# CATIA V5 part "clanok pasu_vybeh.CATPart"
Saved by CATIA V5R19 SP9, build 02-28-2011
Part number: Part1
Material "Black": density 7860 kg/m3, Young's modulus 2e+11 Pa, Poisson ratio 0.266
Bounding box of the stored display mesh (mm): x -56 to 56, y 0 to 19.5, z -16.792 to 199.992
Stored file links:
  D:\CATIA FÓRUM\DISKUSE\clanok pasu_vybeh.CATPart
  C:\Program Files\Dassault Systemes\B19\win_b64\startup\materials\Catalog.CATMaterial
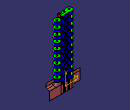
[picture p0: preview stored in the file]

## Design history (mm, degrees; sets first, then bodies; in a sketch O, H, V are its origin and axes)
AxisSystem1 "Main Pulling Direction.1": origin (0, 0, 0), X (1, 0, 0), Y (0, 0, -1), Z (0, 1, 0)
StDynAnalysisRootNodeFeature1 "CATStDynAnalysisRootNodeName"
Set1 "Core.1"
  DatumSurface1 to DatumSurface74
  DatumSurface75 "TrfSurface.322"
Set2 "Cavity.1"
  DatumSurface76
  DatumSurface77
  Boundary1: Boundary DatumSurface77
Set3
  Split1: ToCut Boundary1, Cutting (vertex [face of DatumSurface77 | face of DatumSurface77]; vertex [face of DatumSurface77 | face of DatumSurface77])
  Extrude1: Lim1 27, Lim2 0, Direction xy-plane, Element1 Split1
  Extrapol1: ToExtrapol edge of Extrude1, Support Extrude1, Length 38
  Split2: ToCut {split ToCut Boundary1, Cutting (vertex [face of DatumSurface77 | face of DatumSurface77]; vertex [face of DatumSurface77 | face of DatumSurface77])}, Cutting vertex [face of DatumSurface77 | face of DatumSurface77]
  Split3: ToCut Split2, Cutting (vertex [face of DatumSurface77 | face of DatumSurface77]; vertex [face of DatumSurface77 | face of DatumSurface77])
  Extrude2: Lim1 27, Lim2 0, Direction yz-plane, Element1 Split3
  Extrapol2: ToExtrapol edge of Extrude2, Support Extrude2, Length 27
  Curve1: Elements the part
  Fill1: Boundary ({fillboundary BoundaryWire edge of Extrude1}; Curve1; {fillboundary BoundaryWire edge of Extrapol2, Support Extrapol2}; edge of DatumSurface77)
  Split4: ToCut {split ToCut {split ToCut Boundary1, Cutting (vertex [face of DatumSurface77 | face of DatumSurface77]; vertex [face of DatumSurface77 | face of DatumSurface77])}, Cutting vertex [face of DatumSurface77 | face of DatumSurface77]}, Cutting vertex [face of DatumSurface77 | face of DatumSurface77]
  Split5: ToCut Split4, Cutting vertex [face of DatumSurface77 | face of DatumSurface77]
  Extrude3: Lim1 27, Lim2 0, Direction yz-plane, Element1 Split5
  Boundary2: Boundary edge of Extrude3, BoundaryFrom vertex [face of Extrude3], BoundaryTo {point type OnCurve, Support edge of Extrude3, Length 7.34}
  Boundary3: Boundary edge of Extrapol1, BoundaryFrom vertex [face of Extrapol1], BoundaryTo {point type OnCurve, Support edge of Extrapol1, Length 20.221}
  Blend1: StartLimit {blendlimit Support Extrude3, Curve Boundary2}, EndLimit {blendlimit Support Extrapol1, Curve Boundary3}
  StIsoparamCurveFeature1 "CATStIsoparamCurveFeatureName": Direction {line type PtDir, RefPoint {point type OnSurface, Support Extrapol1, Length 18.8172, Direction (0.825, 0, 0.5652)}, Direction (0, 0, 1000), LENGTH 0, LENGTH 10}, Support Extrapol1, Position {point type OnSurface, Support Extrapol1, Length 18.8172, Direction (0.825, 0, 0.5652)}, BRep face of Extrapol1
  Point1: type OnCurve, Support {split ToCut {split ToCut {split ToCut Boundary1, Cutting (vertex [face of DatumSurface77 | face of DatumSurface77]; vertex [face of DatumSurface77 | face of DatumSurface77])}, Cutting vertex [face of DatumSurface77 | face of DatumSurface77]}, Cutting vertex [face of DatumSurface77 | face of DatumSurface77]}, Length 5.442
  Boundary4: Boundary edge of Extrude3, BoundaryFrom vertex of Split4, BoundaryTo edge of Blend1
  Boundary5: Boundary edge of Extrapol1, BoundaryFrom edge of Blend1, BoundaryTo vertex of Split1
  StIsoparamCurveFeature2 "CATStIsoparamCurveFeatureName": Direction {line type PtDir, RefPoint {point type OnSurface, Support Blend1, Length 6.3176, Direction (-0.9945, -0.0872, 0.0576)}, Direction (1000.5583, 0, -0.2454), LENGTH 0, LENGTH 10}, Position {point type OnSurface, Support Blend1, Length 6.3176, Direction (-0.9945, -0.0872, 0.0576)}, BRep face of Blend1, Support Blend1
  Curve2: Elements the part
  Fill2: Boundary ({fillboundary BoundaryWire Boundary4, Support Extrude3}; {split ToCut {split ToCut {split ToCut Boundary1, Cutting (vertex [face of DatumSurface77 | face of DatumSurface77]; vertex [face of DatumSurface77 | face of DatumSurface77])}, Cutting vertex [face of DatumSurface77 | face of DatumSurface77]}, Cutting vertex [face of DatumSurface77 | face of DatumSurface77]}; Curve2; edge of Blend1)
  Split6: ToCut Blend1, Cutting StIsoparamCurveFeature2
  Split7: ToCut {split ToCut {split ToCut {split ToCut Boundary1, Cutting (vertex [face of DatumSurface77 | face of DatumSurface77]; vertex [face of DatumSurface77 | face of DatumSurface77])}, Cutting vertex [face of DatumSurface77 | face of DatumSurface77]}, Cutting vertex [face of DatumSurface77 | face of DatumSurface77]}, Cutting vertex [face of DatumSurface77 | face of DatumSurface77]
  Split8: ToCut Split7, Cutting edge of Fill2
  Curve3: Elements the part
  Fill3: Boundary ({fillboundary BoundaryWire edge of Blend1, Support Split6}; Curve3; Split8; {fillboundary BoundaryWire edge of Fill2, Support Fill2})
  Boundary6: Boundary edge of Extrapol1, BoundaryFrom edge of Fill3, BoundaryTo vertex of Split1
  Join1: Elements (Extrude3; Fill2; {split ToCut Blend1, Cutting StIsoparamCurveFeature2}; Split6; Fill3; Extrapol1; Fill1; Extrapol2)
  Blend2: StartLimit {blendlimit Curve edge of Fill3}, EndLimit {blendlimit Curve edge of Extrapol1}
  Join2: Elements (Join1; Blend2)
Set4 "Other.1"
  DatumSurface78 to DatumSurface116
Set5 "NoDraft_1deg.1"
  DatumSurface117 to DatumSurface149
Body1 (main body), material "Black"
  Sketch1 on xy-plane, origin (0, 0, 0), H (1, 0, 0), V (0, 1, 0)
    line L1 (0, 0) -> (20, 0)
    arc A1 centre (20, 9) radius 9 from (20, 0) to (20, 18) ccw
    line L2 (20, 18) -> (-20, 18)
    arc A2 centre (-20, 9) radius 9 from (-20, 18) to (-20, 0) ccw
    line L3 (-20, 0) -> (0, 0)
    length L3 = 20
    radius A1 = 9
    radius A2 = 9
    length L2 = 40
    horizontal: L1 H
    tangency: A1 L1, L2 A1, A2 L1, A2 L2, L3 A1
  Pad1: profile Sketch1, direction (0, 0, 1), length 20
  Sketch2 on start face of Pad1, origin (0, 0, 0), H (1, 0, 0), V (0, -1, 0)
    axis line L1 (-36.5413, -9) -> (36.7748, -9)
    reference projected line E1 (0, 0) -> (20, 0) from edge [face of Pad1 from Sketch1.L1 | end face of Pad1]
    reference projected line E2 (20, -18) -> (-20, -18) from edge [face of Pad1 from Sketch1.L2 | end face of Pad1]
    circle A1 centre (-20, -9) radius 3
    point P3 (-20, -9)
    circle A2 centre (20, -9) radius 3
    point P4 (20, -9)
    radius A2 = 3
    radius A1 = 3
    distance P4 P3 = 40
    distance P4 V = 20
    horizontal: L1 H
    symmetry: E1 E2 L1
    coincidence: P3 L1, P4 L1
  Pocket1: profile Sketch2, direction (0, 0, 1), length 20
  Sketch3 on start face of Pad1, origin (0, 0, 0), H (1, 0, 0), V (0, -1, 0)
    line L1 (10.5, 0) -> (30.5, 0)
    line L2 (30.5, 0) -> (30.5, -18)
    point P1 (30.5, 0)
    arc A1 centre (18.5, -10) radius 8 from (10.5, -10) to (16.7362, -17.8031) ccw
    point P5 (30.5, 0)
    point P6 (30.5, -18)
    line L3 (10.5, 0) -> (10.5, -10)
    arc A2 centre (16.7141, -17.9007) radius 0.1 from (16.7362, -17.8031) to (16.7025, -18) cw
    point P7 (16.7362, -17.8031)
    line L4 (16.7025, -18) -> (30.5, -18)
    length L2 = 18
    radius A1 = 8
    length L1 = 20
    distance L3 V = 10.5
    distance L1 H = 0
    radius A2 = 0.1
    distance P7 P6 = 13.7652
    horizontal: L1 H
    vertical: L2 V
    tangency: L3 A1, A2 A1, L4 A1
    coincidence: P5 P1
    parallelism: L4 L1
  Pocket2: profile Sketch3, direction (0, 0, 1), length 20, opposite side length -9.8
  Sketch4 on start face of Pad1, origin (0, 0, 0), H (1, 0, 0), V (0, -1, 0)
    point P1 (-10.5, 0)
    line L1 (-10.5, 0) -> (-29.2193, 0)
    line L2 (-29.2193, 0) -> (-29.2193, -18)
    arc A1 centre (-18.5, -10) radius 8 from (-16.7362, -17.8031) to (-10.5, -10) ccw
    line L3 (-10.5, -10) -> (-10.5, 0)
    point P6 (-10.5, 0)
    arc A2 centre (-16.7141, -17.9007) radius 0.1 from (-16.7362, -17.8031) to (-16.7025, -18) ccw
    point P7 (-16.7362, -17.8031)
    line L4 (-16.7025, -18) -> (-29.2193, -18)
    length L2 = 18
    distance L3 V = 10.5
    radius A1 = 8
    length L1 = 18.7193
    radius A2 = 0.1
    distance L2 P7 = 12.4831
    coincidence: P1 H, P6 H, P1 P6
    horizontal: L1 H
    vertical: L2 V
    tangency: L3 A1, A2 A1, L4 A1
    parallelism: L4 L1
  Pocket3: profile Sketch4, direction (0, 0, 1), length 10.2
  Sketch5 on face of Pad1 from Sketch1.L1, origin (0, 0, 0), H (1, 0, 0), V (0, 0, 1)
    point P1 (-6.75, 0)
    line L1 (-6.75, 0) -> (6.75, 0)
    line L2 (6.75, 0) -> (6.75, 20)
    line L3 (6.75, 20) -> (-6.75, 20)
    line L4 (-6.75, 20) -> (-6.75, 0)
    length L4 = 20
    length L3 = 13.5
    distance V L2 = 6.75
    coincidence: P1 H
    horizontal: L1 H, L3 H
    vertical: L2 V, L4 V
  Pocket4: profile Sketch5, direction (0, 1, 0), length 10
  Draft1: PullDir end face of Pocket4, Angle 7, SupportToDraft (face of Pocket4 from Sketch5.L4; face of Pocket4 from Sketch5.L2), Neutral end face of Pocket4
  Sketch6 on face of Pad1 from Sketch1.L3, origin (0, 0, 0), H (1, 0, 0), V (0, 0, 1)
    point P1 (-11.5, 0)
    line L1 (-11.5, 0) -> (11.5, 0)
    line L2 (11.5, 0) -> (11.5, 20)
    line L3 (11.5, 20) -> (-11.5, 20)
    line L4 (-11.5, 20) -> (-11.5, 0)
    length L3 = 23
    length L2 = 20
    distance V L2 = 11.5
    coincidence: P1 H
    horizontal: L1 H, L3 H
    vertical: L2 V, L4 V
  Pocket5: profile Sketch6, direction (0, 1, 0), length 2.5
  Sketch7 on start face of Pad1, origin (0, 0, 0), H (1, 0, 0), V (0, -1, 0)
    point P1 (11.5, 0)
    line L1 (11.5, 0) -> (11.5, -2.5)
    point P2 (11.5, -2.5)
    line L2 (11.5, -2.5) -> (17.5, 0)
    point P3 (17.5, 0)
    line L3 (17.5, 0) -> (11.5, 0)
    axis line L4 (0, 6.926) -> (0, -8.9844)
    point P4 (0, 6.926)
    point P6 (-11.5, 0)
    point P7 (-11.5, -2.5)
    point P8 (-17.5, 0)
    line L5 (-11.5, 0) -> (-11.5, -2.5)
    line L6 (-11.5, -2.5) -> (-17.5, 0)
    line L7 (-17.5, 0) -> (-11.5, 0)
    distance V L1 = 11.5
    length L3 = 6
    length L1 = 2.5
    coincidence: P1 H, P3 H, P4 V
    vertical: L1 V, L4 V
    horizontal: L3 H
    symmetry: P1 P6 L4, P2 P7 L4, P3 P8 L4, L1 L5 L4, L2 L6 L4, L3 L7 L4
  Pocket6: profile Sketch7, direction (0, 0, 1), length 20
  Fillet1: radius 8, on edge [face of Pocket6 from Sketch7.L6 | face of Pad1 from Sketch1.L3]
  Fillet2: radius 1, on edge [face of Pocket6 from Sketch7.L6 | end face of Pocket5]; edge [face of Pocket6 from Sketch7.L2 | end face of Pocket5]
  Fillet3: radius 2, on edge [end face of Pocket5 | face of Pocket4 from Sketch5.L4]; edge [end face of Pocket5 | face of Pocket4 from Sketch5.L2]
  Fillet4: radius 1, on edge [face of Pocket4 from Sketch5.L4 | end face of Pocket4]; edge [face of Pocket4 from Sketch5.L2 | end face of Pocket4]
  Fillet5: radius 8, on edge [face of Pad1 from Sketch1.L1 | face of Pocket6 from Sketch7.L2]
  Sketch8 on face of Pad1 from Sketch1.L1, origin (0, 0, 0), H (1, 0, 0), V (0, 0, 1)
    point P2 (-19.9966, 20)
    point P4 (20.0034, 0)
    line L1 (-19.9966, 20) -> (-10.5, 16.25)
    point P5 (-10.5, 16.25)
    line L2 (-10.5, 16.25) -> (-6.2016, 16.25)
    line L3 (-6.2016, 16.25) -> (7.381, 6.55)
    line L4 (7.381, 6.55) -> (10.5, 6.55)
    point P8 (10.5, 6.55)
    line L5 (10.5, 6.55) -> (20.0034, 9.8)
    line L6 (20.0034, 9.8) -> (20.0034, 0)
    line L7 (20.0034, 0) -> (10.5, 3.75)
    point P9 (10.5, 3.75)
    line L8 (10.5, 3.75) -> (6.4838, 3.75)
    line L9 (6.4838, 3.75) -> (-7.0988, 13.45)
    line L10 (-7.0988, 13.45) -> (-10.5, 13.45)
    point P12 (-10.5, 13.45)
    line L11 (-10.5, 13.45) -> (-19.9966, 10.2)
    line L12 (-19.9966, 10.2) -> (-19.9966, 20)
    construction line L13 (-10.5, -2.6535) -> (-10.5, 25.1886)
    construction line L14 (10.5, 24.8564) -> (10.5, -2.3213)
    reference projected line E1 (-10.5, 0) -> (-10.5, 10.2) from edge [end face of Pocket5 | face of Pocket3 from Sketch4.L3]
    reference projected line E2 (10.5, 20) -> (10.5, 9.8) from edge [end face of Pocket5 | face of Pocket2 from Sketch3.L3]
    reference projected line E3 (-7.4552, 20) -> (-9.4403, 20) from edge [end face of Pad1 | face of Fillet3]
    reference projected line E4 (7.4552, 0) -> (9.4403, 0) from edge [start face of Pad1 | face of Fillet3]
    distance P12 V = 10.5
    length L12 = 9.8
    length L6 = 9.8
    distance P2 H = 20
    distance E3 L2 = 3.75
    distance L8 E4 = 3.75
    distance L10 L2 = 2.8
    distance L4 L8 = 2.8
    distance L9 L3 = 2.8
    horizontal: L2 H, L4 H, L10 H
    vertical: L6 V, L12 V, L13 V, L14 V
    coincidence: L13 E1, L14 E2, P4 H, P9 L14, P8 L14, P5 L13
    fix: L12, L6, L3
  Pad2: profile Sketch8, direction (0, -1, 0), length -11
  Sketch9 on end face of Pad1, origin (0, 0, 20), H (1, 0, 0), V (0, 1, 0)
    circle A1 centre (-20, 9) radius 3.05
    circle A2 centre (20, 9) radius 3.05
    fix: A2, A1
  Pocket7: profile Sketch9, direction (0, 0, -1), length 20
  Sketch10 on face of Pad2, origin (0, 0, 0), H (1, 0, 0), V (0, 0, 1)
    line L1 (-10.5, 6.55) -> (-7.9668, 6.55)
    line L2 (-7.9668, 6.55) -> (7.1589, 16.25)
    line L3 (7.1589, 16.25) -> (10.5, 16.25)
    line L4 (10.5, 16.25) -> (10.5, 13.45)
    line L5 (10.5, 13.45) -> (7.9796, 13.45)
    line L6 (7.9796, 13.45) -> (-7.1461, 3.75)
    line L7 (-7.1461, 3.75) -> (-10.5, 3.75)
    line L8 (-10.5, 3.75) -> (-10.5, 6.55)
    reference projected line E1 (9.4403, 20) -> (7.4552, 20) from edge [end face of Pad1 | face of Fillet3]
    reference projected line E2 (-9.4403, 0) -> (-7.4552, 0) from edge [start face of Pad1 | face of Fillet3]
    distance L8 L4 = 21
    distance L4 V = 10.5
    length L8 = 2.8
    length L4 = 2.8
    distance L2 L6 = 2.8
    distance L3 E1 = 3.75
    distance L7 E2 = 3.75
    horizontal: L1 H, L3 H, L5 H, L7 H
    vertical: L4 V, L8 V
    fix: L2
  Pad3: profile Sketch10, direction (0, -1, 0), length -14
  Draft2: PullDir face of Pad3, Angle -1.5, SupportToDraft (face of Pad2 from Sketch8.L7; face of Pad2 from Sketch8.L8; face of Pad2 from Sketch8.L9; face of Pad3 from Sketch10.L6; face of Pad3 from Sketch10.L7; face of Pad3 from Sketch10.L2; face of Pad3 from Sketch10.L1; face of Pad2 from Sketch8.L4; face of Pad2 from Sketch8.L3; face of Pad3 from Sketch10.L3; face of Pad3 from Sketch10.L2; face of Pad2 from Sketch8.L3; face of Pad2 from Sketch8.L2; face of Pad2 from Sketch8.L1; face of Pad3 from Sketch10.L5; face of Pad3 from Sketch10.L6; face of Pad2 from Sketch8.L9; face of Pad2 from Sketch8.L10; face of Pad2 from Sketch8.L11; face of Pad2 from Sketch8.L5), Neutral face of Pad3
  Draft3: PullDir face of Pad3, Angle -3, SupportToDraft (face of Pad2 from Sketch8.L9; face of Pad3 from Sketch10.L2; face of Pad2 from Sketch8.L3; face of Pad3 from Sketch10.L6), Neutral face of Pad3
  Fillet6: radius 1, on edge [face of Pad2 from Sketch8.L1 | face of Fillet1]; edge [face of Pad2 from Sketch8.L1 | face of Pocket6 from Sketch7.L6]; edge [face of Pad2 from Sketch8.L1 | face of Fillet2]; edge [face of Pad2 from Sketch8.L1 | end face of Pocket5]; edge [face of Pad2 from Sketch8.L2 | end face of Pocket5]; edge [face of Pad2 from Sketch8.L2 | face of Fillet3]; edge [face of Pad2 from Sketch8.L2 | face of Pocket4 from Sketch5.L4]; edge [face of Pad2 from Sketch8.L2 | face of Fillet4]; edge [face of Pad2 from Sketch8.L3 | end face of Pocket4]; edge [face of Pad2 from Sketch8.L2 | face of Pad2 from Sketch8.L3]; edge [face of Pad2 from Sketch8.L3 | face of Pad3 from Sketch10.L2]; edge [face of Pad3 from Sketch10.L2 | end face of Pocket4]; edge [face of Pad2 from Sketch8.L3 | face of Fillet4]; edge [face of Pad3 from Sketch10.L2 | face of Fillet4]; edge [face of Pad3 from Sketch10.L2 | face of Pocket4 from Sketch5.L2]; edge [face of Pad3 from Sketch10.L3 | face of Pocket4 from Sketch5.L2]; edge [face of Pad3 from Sketch10.L2 | face of Pad3 from Sketch10.L3]; edge [face of Pad3 from Sketch10.L3 | face of Fillet3]; edge [face of Pad3 from Sketch10.L3 | end face of Pocket5]; edge [face of Pad2 from Sketch8.L1 | face of Pad2 from Sketch8.L2]
  Fillet7: radius 1, on edge [face of Pad2 from Sketch8.L11 | face of Fillet1]; edge [face of Pad2 from Sketch8.L11 | face of Pocket6 from Sketch7.L6]; edge [face of Pad2 from Sketch8.L11 | face of Fillet2]; edge [face of Pad2 from Sketch8.L11 | end face of Pocket5]; edge [face of Pad2 from Sketch8.L10 | end face of Pocket5]; edge [face of Pad2 from Sketch8.L10 | face of Fillet3]; edge [face of Pad2 from Sketch8.L9 | face of Pad2 from Sketch8.L10]; edge [face of Pad2 from Sketch8.L11 | face of Pad2 from Sketch8.L10]; edge [face of Pad2 from Sketch8.L9 | face of Pocket4 from Sketch5.L4]; edge [face of Pad2 from Sketch8.L9 | end face of Pocket4]; edge [face of Pad2 from Sketch8.L9 | face of Fillet4]; edge [face of Pad3 from Sketch10.L2 | face of Pad2 from Sketch8.L9]; edge [face of Pad3 from Sketch10.L2 | end face of Pocket4]; edge [face of Pad3 from Sketch10.L2 | face of Fillet4]; edge [face of Pad3 from Sketch10.L2 | face of Pocket4 from Sketch5.L4]; edge [face of Pad3 from Sketch10.L2 | face of Fillet3]; edge [face of Pad3 from Sketch10.L1 | face of Fillet3]; edge [face of Pad3 from Sketch10.L1 | end face of Pocket5]
  Fillet8: radius 1, on edge [face of Pad3 from Sketch10.L5 | end face of Pocket5]; edge [face of Pad3 from Sketch10.L5 | face of Fillet3]; edge [face of Pad3 from Sketch10.L6 | face of Pad3 from Sketch10.L5]; edge [face of Pad3 from Sketch10.L6 | face of Fillet3]; edge [face of Pad3 from Sketch10.L6 | face of Pocket4 from Sketch5.L2]; edge [face of Pad3 from Sketch10.L6 | face of Fillet4]; edge [face of Pad3 from Sketch10.L6 | end face of Pocket4]; edge [face of Pad3 from Sketch10.L6 | face of Pad2 from Sketch8.L3]; edge [face of Pad2 from Sketch8.L3 | end face of Pocket4]; edge [face of Pad2 from Sketch8.L3 | face of Fillet4]; edge [face of Pad2 from Sketch8.L3 | face of Pocket4 from Sketch5.L2]; edge [face of Pad2 from Sketch8.L3 | face of Pad2 from Sketch8.L4]; edge [face of Pad2 from Sketch8.L3 | face of Fillet3]; edge [face of Pad2 from Sketch8.L4 | face of Fillet3]; edge [face of Pad2 from Sketch8.L4 | end face of Pocket5]; edge [face of Pad2 from Sketch8.L5 | face of Pad2 from Sketch8.L4]; edge [face of Pad2 from Sketch8.L5 | end face of Pocket5]; edge [face of Pad2 from Sketch8.L5 | face of Fillet2]; edge [face of Pad2 from Sketch8.L5 | face of Pocket6 from Sketch7.L2]; edge [face of Pad2 from Sketch8.L5 | face of Fillet5]
  Fillet9: radius 1, on edge [face of Pad3 from Sketch10.L7 | end face of Pocket5]; edge [face of Pad3 from Sketch10.L7 | face of Fillet3]; edge [face of Pad3 from Sketch10.L7 | face of Pad3 from Sketch10.L6]; edge [face of Pad3 from Sketch10.L7 | face of Pocket4 from Sketch5.L4]; edge [face of Pad3 from Sketch10.L6 | face of Pad2 from Sketch8.L9]; edge [face of Pad3 from Sketch10.L6 | end face of Pocket4]; edge [face of Pad2 from Sketch8.L9 | end face of Pocket4]; edge [face of Pad3 from Sketch10.L6 | face of Pocket4 from Sketch5.L4]; edge [face of Pad3 from Sketch10.L6 | face of Fillet4]; edge [face of Pad2 from Sketch8.L9 | face of Pad2 from Sketch8.L8]; edge [face of Pad2 from Sketch8.L9 | face of Fillet4]; edge [face of Pad2 from Sketch8.L8 | face of Fillet4]; edge [face of Pad2 from Sketch8.L8 | face of Pocket4 from Sketch5.L2]; edge [face of Pad2 from Sketch8.L8 | face of Fillet3]; edge [face of Pad2 from Sketch8.L8 | end face of Pocket5]; edge [face of Pad2 from Sketch8.L8 | face of Pad2 from Sketch8.L7]; edge [face of Pad2 from Sketch8.L7 | end face of Pocket5]; edge [face of Pad2 from Sketch8.L7 | face of Fillet2]; edge [face of Pad2 from Sketch8.L7 | face of Pocket6 from Sketch7.L2]; edge [face of Pad2 from Sketch8.L7 | face of Fillet5]
  Fillet10: radius 2, on edge [face of Pad3 | face of Pad3] (x2)
  Sketch11 on end face of Pocket4, origin (0, 10, 0), H (1, 0, 0), V (0, 0, 1)
    circle A1 centre (0, 20) radius 3.3
    point P1 (0, 20)
    circle A2 centre (0, 0) radius 3.3
    radius A1 = 3.3
    radius A2 = 3.3
    distance P1 H = 20
    coincidence: P1 V
  Pocket8: profile Sketch11, direction (0, -1, 0), length -1
  Fillet11: radius 0.2, on edge [end face of Pocket4 | face of Pocket8 from Sketch11.A2]; edge [face of Pocket8 from Sketch11.A2 | end face of Pocket8]; edge [end face of Pocket4 | face of Pocket8 from Sketch11.A1]; edge [face of Pocket8 from Sketch11.A1 | end face of Pocket8]
  RectPattern1: of the body so far, direction 1 instances 1, spacing 20, along face of Pad1 from Sketch1.L2, direction 2 instances 10, spacing 20, along face of Pad1 from Sketch1.L2
  Draft4: PullDir face of Pad3, Angle -1.5, SupportToDraft (end face of Pocket3; face of RectPattern1; face of RectPattern1; face of RectPattern1; face of RectPattern1; face of RectPattern1; face of RectPattern1; face of RectPattern1; face of RectPattern1; face of RectPattern1; face of RectPattern1; face of RectPattern1; face of RectPattern1; face of RectPattern1; face of RectPattern1; face of RectPattern1; face of RectPattern1; face of RectPattern1; end face of Pad1; face of RectPattern1; face of RectPattern1; face of RectPattern1; face of RectPattern1; face of RectPattern1; face of RectPattern1; face of RectPattern1; face of RectPattern1; face of RectPattern1; face of RectPattern1; face of RectPattern1; face of RectPattern1; face of RectPattern1; face of RectPattern1; face of RectPattern1; face of RectPattern1; face of RectPattern1; face of RectPattern1; face of RectPattern1; start face of Pad1), Neutral face of RectPattern1
  Sketch12 on start face of Pocket2, origin (0, 0, 9.8), H (1, 0, 0), V (0, 1, 0)
    point P1 (-30.599, 0)
    line L1 (-30.599, 0) -> (30.8667, 0)
    line L2 (30.8667, 0) -> (30.8667, 18)
    line L3 (30.8667, 18) -> (-30.599, 18)
    line L4 (-30.599, 18) -> (-30.599, 0)
    distance L3 L1 = 18
    distance L2 V = 30.8667
    length L3 = 61.4657
    coincidence: P1 H
    horizontal: L1 H, L3 H
    vertical: L2 V, L4 V
  Pocket9: profile Sketch12, direction (0, 0, 1), length -11, opposite side length -0.4
  Fillet12: on edge [face of RectPattern1 | face of RectPattern1] (x34); edge [end face of Pad1 | face of RectPattern1] (x2)
  Sketch13 on end face of Pocket3, origin (0, 0.2792, 10.664), H (1, 0, 0), V (0, -0.9997, 0.0262)
    line L1 (-33.1892, 1.2415) -> (32.5509, 1.2415)
    line L2 (32.5509, 1.2415) -> (32.5509, -18.2673)
    line L3 (32.5509, -18.2673) -> (-33.1892, -18.2673)
    line L4 (-33.1892, -18.2673) -> (-33.1892, 1.2415)
    length L2 = 19.5088
    length L1 = 65.7401
    distance V L2 = 32.5509
    distance H L1 = 1.2415
    horizontal: L1 H, L3 H
    vertical: L2 V, L4 V
  Pocket10: profile Sketch13, direction (0, 0.0262, 0.9997), length -1.8
  Fillet13: on edge [face of RectPattern1 | face of Pocket2 from Sketch3.A1]; edge [face of RectPattern1 | face of Pad3]; edge [face of RectPattern1 | face of RectPattern1] (x34)
  Fillet14: radius 0.3, on edge [face of RectPattern1 | face of RectPattern1]
  Fillet15: radius 0.3, on edge [face of RectPattern1 | face of RectPattern1]
  Fillet16: radius 0.3, on edge [face of RectPattern1 | face of RectPattern1] (x10)
  Fillet17: radius 0.3, on edge [face of RectPattern1 | face of RectPattern1]
  Fillet18: radius 0.3, on edge [face of RectPattern1 | face of RectPattern1] (x3)
  Fillet19: radius 0.3, on edge [face of RectPattern1 | face of RectPattern1] (x3)
  Fillet20: radius 0.3, on edge [face of RectPattern1 | face of RectPattern1] (x3)
  Fillet21: radius 0.3, on edge [face of RectPattern1 | face of RectPattern1] (x6)
  Fillet22: radius 0.3, on edge [face of RectPattern1 | face of RectPattern1] (x12); edge [face of Pad3 from Sketch10.L6 | face of Pad3]
  Fillet23: radius 0.3, on edge [face of Pad2 from Sketch8.L9 | face of Pad3]
  Fillet24: radius 0.3, on edge [face of Pocket10 | face of Pad3]
  Plane1: type Offset, RefPlane zx-plane, Offset 18
  Sketch14 on Plane1, origin (0, 18, 0), H (-1, 0, 0), V (0, 0, 1)
  Sketch15 on Plane1, origin (0, 18, 0), H (-1, 0, 0), V (0, 0, 1)
    line L1 (0, 0) -> (-30, -30)
    line L2 (0, 5) -> (38.1191, -33.1191)
    point P2 (0, 5)
    distance H P2 = 5
    length L2 = 53.9085
    fix: L1
    coincidence: P2 V
    perpendicularity: L2 L1
  Sketch16 on zx-plane, origin (0, 0, 0), H (-1, 0, 0), V (0, 0, 1)
    line L1 (0, 0) -> (-30, -30)
    point P2 (0, 5)
    line L2 (0, 5) -> (37.7003, -32.7003)
    length L2 = 53.3163
    distance P2 H = 5
    fix: L1
    coincidence: P2 V
    perpendicularity: L2 L1
  Plane2: type 2Lines, Element1 Sketch15.L1, Element2 Sketch16
  Sketch17 on Plane2, origin (0, 0, 0), H (0, 1, 0), V (-0.7071, 0, 0.7071)
    line L1 (19.5, -12.2) -> (17.8, -10.5)
    point P1 (19.5, -12.2)
    line L2 (19.5, -12.2) -> (17.8, -13.9)
    line L3 (17.8, -13.9) -> (17.8, -10.5)
    reference projected line E1 (18, 0) -> (18, -42.4264) from Sketch15.L1
    axis line L4 (6.75, -4.9777) -> (6.75, -21.6177)
    distance E1 P1 = 1.5
    angle L3 L1 = 45
    angle L3 L2 = 45
    distance P1 H = 12.2
    distance L3 V = 17.8
    distance P1 L4 = 12.75
    vertical: L3 V, L4 V
  Shaft1: profile Sketch17, axis Sketch17.L4, angle 29, second angle 29
  RectPattern2: of Shaft1, direction 1 instances 2, spacing 14.5, along face of RectPattern1, direction 2 instances 11, spacing 20, along face of RectPattern1
  Sketch18 on Plane2, origin (0, 0, 0), H (0, 1, 0), V (-0.7071, 0, 0.7071)
    line L1 (17.8, -6.8) -> (17.8, -10.2)
    line L2 (17.8, -10.2) -> (19.5, -8.5)
    point P3 (19.5, -8.5)
    line L3 (19.5, -8.5) -> (17.8, -6.8)
    reference projected line E1 (18, 0) -> (18, -42.4264) from Sketch15.L1
    reference projected line E2 (0, 0) -> (0, -42.4264) from Sketch16.L1
    axis line L4 (5.05, 2.9767) -> (5.05, -7.6001)
    angle L1 L3 = 45
    angle L2 L1 = 45
    distance E1 P3 = 1.5
    distance L1 E2 = 17.8
    distance L4 L1 = 12.75
    distance P3 H = 8.5
    vertical: L1 V, L4 V
  Shaft2: profile Sketch18, axis Sketch18.L4, angle 29, second angle 29
  RectPattern3: of Shaft2, direction 1 instances 2, spacing 14.5, along face of RectPattern1, direction 2 instances 11, spacing 20, along face of RectPattern1
  Plane3: type 2Lines, Element1 Sketch15.L2, Element2 Sketch16.L2
  Sketch19 on Plane3, origin (-2.5, 0, 2.5), H (0, 1, 0), V (0.7071, 0, 0.7071)
    line L1 (17.8, 0.2) -> (17.8, -3.2)
    line L2 (17.8, -3.2) -> (19.5, -1.5)
    point P3 (19.5, -1.5)
    line L3 (19.5, -1.5) -> (17.8, 0.2)
    axis line L4 (6.75, 6.3785) -> (6.75, -7.9529)
    reference projected line E1 (18, 3.5355) -> (18, -50.373) from Sketch15.L2
    reference projected line E2 (0, 3.5355) -> (0, -49.7807) from Sketch16.L2
    angle L1 L3 = 45
    angle L2 L1 = 45
    distance P3 E1 = 1.5
    distance P3 L4 = 12.75
    distance E2 L1 = 17.8
    distance P3 H = 1.5
    vertical: L1 V, L4 V
  Shaft3: profile Sketch19, axis Sketch19.L4, angle 29, second angle 29
  RectPattern4: of Shaft3, direction 1 instances 1, spacing 1.5, along face of RectPattern1, direction 2 instances 10, spacing 20, along face of RectPattern1, Nu 2
  Sketch20 on Plane3, origin (-2.5, 0, 2.5), H (0, 1, 0), V (0.7071, 0, 0.7071)
    line L1 (17.8, 3.9) -> (17.8, 0.5)
    line L2 (17.8, 0.5) -> (19.5, 2.2)
    point P3 (19.5, 2.2)
    line L3 (19.5, 2.2) -> (17.8, 3.9)
    axis line L4 (6.75, 6.7846) -> (6.75, -4.6426)
    reference projected line E1 (18, 3.5355) -> (18, -50.373) from Sketch15.L2
    angle L3 L1 = 45
    angle L1 L2 = 45
    distance P3 E1 = 1.5
    distance L1 V = 17.8
    distance L4 P3 = 12.75
    distance H P3 = 2.2
    vertical: L1 V, L4 V
  Shaft4: profile Sketch20, axis Sketch20.L4, angle 29, second angle 29
  RectPattern5: of Shaft4, direction 1 instances 1, spacing 1.5, along face of RectPattern1, direction 2 instances 10, spacing 20, along face of RectPattern1, Nu 2
  Sketch21 on face of Pocket10, origin (0, 0.2792, 10.664), H (1, 0, 0), V (0, -0.9997, 0.0262)
    line L1 (-35.236, 9.6787) -> (42.2526, 9.6787)
    line L2 (42.2526, 9.6787) -> (42.2526, -27.2541)
    line L3 (42.2526, -27.2541) -> (-35.236, -27.2541)
    line L4 (-35.236, -27.2541) -> (-35.236, 9.6787)
    distance V L2 = 42.2526
    length L2 = 36.9327
    length L3 = 77.4887
    distance L3 H = 27.2541
    horizontal: L1 H, L3 H
    vertical: L2 V, L4 V
  Pocket11: profile Sketch21, direction (0, 0.0262, 0.9997), length -25.8
  Sketch22 on face of RectPattern1, origin (0, 18, 0), H (-1, 0, 0), V (0, 0, 1)
    line L1 (-11.1999, 11.3) -> (13.4258, 11.3)
    line L2 (13.4258, 11.3) -> (13.4258, 9.8)
    line L3 (13.4258, 9.8) -> (-11.1999, 9.8)
    line L4 (-11.1999, 9.8) -> (-11.1999, 11.3)
    distance H L1 = 11.3
    length L3 = 24.6257
    length L2 = 1.5
    distance L2 V = 13.4258
    horizontal: L1 H, L3 H
    vertical: L2 V, L4 V
  Pocket12: profile Sketch22, direction (0, -1, 0), length -1.6
  Fillet25: radius 0.3, on edge [face of Pocket11 | face of Pocket12]
  Fillet26: radius 0.3, on edge [face of Pocket11 | face of Pocket12] (x3)
  Fillet27: radius 0.3, on edge [face of RectPattern1 | face of RectPattern1]
  Fillet28: radius 0.3, on edge [face of RectPattern1 | face of RectPattern1]
  Fillet29: radius 0.3, on edge [face of RectPattern1 | face of RectPattern1] (x5)
  Fillet30: radius 0.3, on edge [face of RectPattern1 | face of Pocket12]
  Plane4: type Offset, RefPlane Plane1, Offset -0.308
  Plane5: type Offset, RefPlane zx-plane, Offset 9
